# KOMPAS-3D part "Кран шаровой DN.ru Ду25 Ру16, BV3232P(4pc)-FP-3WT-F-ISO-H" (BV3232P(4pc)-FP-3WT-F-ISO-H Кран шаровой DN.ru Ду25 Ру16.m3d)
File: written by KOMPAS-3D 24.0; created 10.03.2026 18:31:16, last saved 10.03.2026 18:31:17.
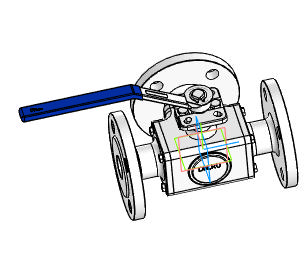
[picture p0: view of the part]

Document properties: Автор: R2D2; Полное имя файла: E:\Работа\Зайцев\BV3232P(4pc)-FP-3WT-F-ISO-H Кран шаровой DN.ru Ду15-100 Ру16\DN25\BV3232P(4pc)-FP-3WT-F-ISO-H Кран шаровой DN.ru Ду25 Ру16.m3d

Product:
- Part/product: Кран шаровой DN.ru Ду25 Ру16  | designation BV3232P(4pc)-FP-3WT-F-ISO-H
    Масса: 5.6
    Раздел спецификации: Прочие изделия
    Примечание: D160-36348

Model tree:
1. Операция без истории:1

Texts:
  BV3232P(4pc)-FP-3WT-F-ISO-H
